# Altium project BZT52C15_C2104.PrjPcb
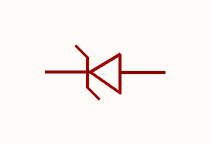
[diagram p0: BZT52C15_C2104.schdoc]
1 sheet, 1 parts. Net scope: global (net labels, ports and power ports of the same name join across sheets).

## Sheet BZT52C15_C2104.schdoc
size 127 x 101 mm

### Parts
ZD?  bzt52c15_c2104  [SOD-123_L2.8-W1.8-LS3.7-RD]  (value not drawn)

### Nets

Not connected (* = marked no-connect by the designer): ZD? 1(K) 2(A)

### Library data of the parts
ZD? = bzt52c15_c2104: 二极管配置:1个独立式;稳压值(标称值):15V;稳压值(范围):13.8V~15.6V;耗散功率(Pd):500mW;; Manufacturer: CJ(江苏长电/长晶); AddInBom: yes; ModelId: 7884390a25fb4c08947731ebfba7e3f8; ModelTransform: 144.8816,62.992,0,0,0,0,0,0,0; Diode Configuration: 1个独立式; Zener Voltage(Nom): 15V; Reverse Leakage Current (Ir): 100nA; Pd - Power Dissipation: 500mW; Impedance(Zzt): 30Ω; Impedance(Zzk): 200Ω; Operating Junction Temperature Range: -55℃~+150℃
